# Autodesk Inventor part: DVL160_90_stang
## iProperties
Created: 2009-09
Part Number: DVL160_90_stang
Document SubType Name: Modeling
Designer: TB
Mass: 2749.61 g
Surface Area: 1412.59 cm^2
Volume: 2749.61 cm^3
Density: 1 g/cm^3
Author: TB
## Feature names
1. Revolution1
2. Fillet1
3. Revolution2
